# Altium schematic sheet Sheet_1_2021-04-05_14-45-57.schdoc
size 231 x 139 mm
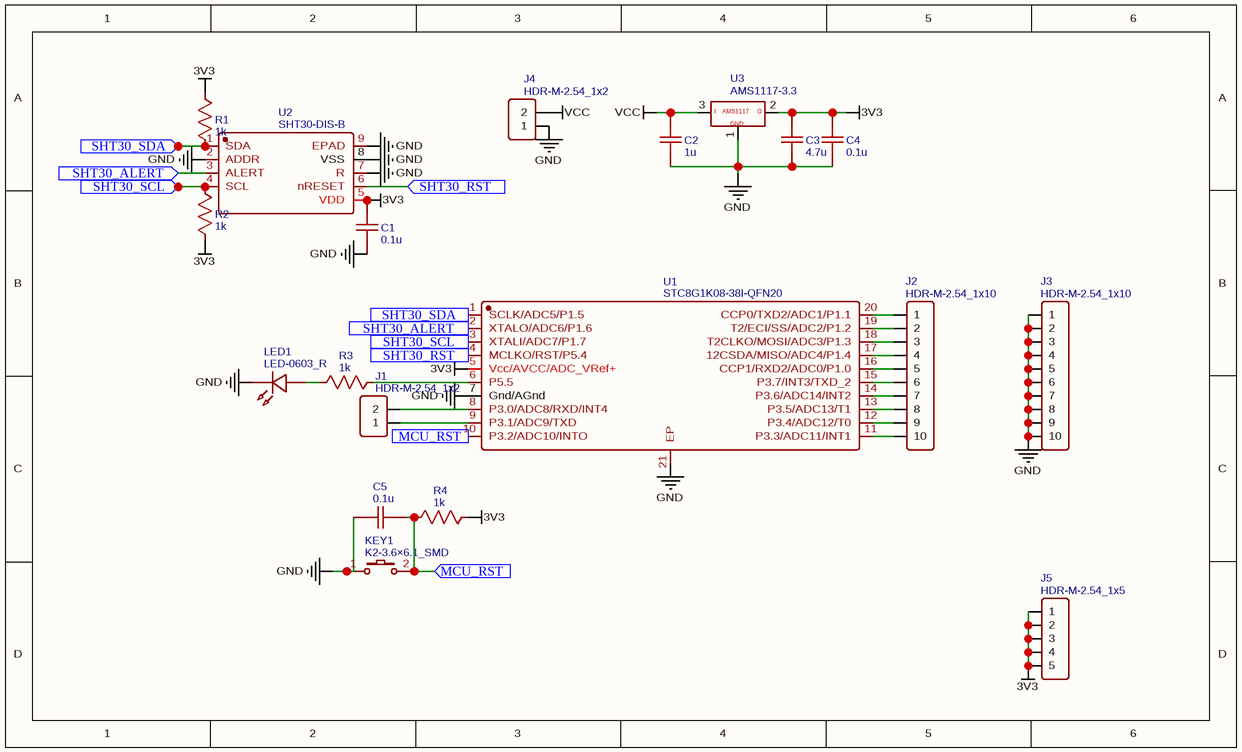
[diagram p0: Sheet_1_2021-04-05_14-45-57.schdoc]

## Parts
C1  0.1u  [C0603]
C2  1u  [C0603]
C3  4.7u  [C0603]
C4  0.1u  [C0603]
C5  0.1u  [C0603]
J1  HDR-M-2.54_1x2  [HDR-M-2.54_1X2]
J2  HDR-M-2.54_1x10  [HDR-M-2.54_1X10]
J3  HDR-M-2.54_1x10  [HDR-M-2.54_1X10]
J4  HDR-M-2.54_1x2  [HDR-M-2.54_1X2]
J5  HDR-M-2.54_1x5  [HDR-M-2.54_1X5]
KEY1  K2-3.6×6.1_SMD  [KEY-SMD_2P-L6.2-W3.6-LS8.0]
LED1  LED-0603_R  [LED0603_RED]
R1  1k  [R0603]
R2  1k  [R0603]
R3  1k  [R0603]
R4  1k  [R0603]
U1  STC8G1K08-38I-QFN20  [TQFN-20L_L3.0-W3.0-P0.40-BL-EP]
U2  SHT30-DIS-B  [DFN-8_L2.5-W2.5-P0.50-BL-EP]
U3  AMS1117-3.3  [SOT-89]

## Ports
MCU_RST (in), SHT30_ALERT (in), SHT30_RST (in), SHT30_SCL (in), SHT30_SDA (in)

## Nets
3V3: C1.2 C3.2 C4.2 J5.1 J5.2 J5.3 J5.4 J5.5 R1.2 R2.1 R4.1 U1.5(Vcc/AVCC/ADC_VRef+) U2.5(VDD) U3.2
GND: C1.1 C2.1 C3.1 C4.1 C5.1 J3.1 J3.2 J3.3 J3.4 J3.5 J3.6 J3.7 J3.8 J3.9 J3.10 J4.1 KEY1.1 LED1.2 U1.7(Gnd/AGnd) U1.21(EP) U2.2(ADDR) U2.7(R) U2.8(VSS) U2.9(EPAD) U3.1
VCC: C2.2 J4.2 U3.3
MCU_RST: C5.2 KEY1.2 R4.2 U1.10(P3.2/ADC10/INTO) ; port MCU_RST
SHT30_ALERT: U1.2(XTALO/ADC6/P1.6) U2.3(ALERT) ; port SHT30_ALERT
SHT30_RST: U1.4(MCLKO/RST/P5.4) U2.6(nRESET) ; port SHT30_RST
SHT30_SCL: R2.2 U1.3(XTALI/ADC7/P1.7) U2.4(SCL) ; port SHT30_SCL
SHT30_SDA: R1.1 U1.1(SCLK/ADC5/P1.5) U2.1(SDA) ; port SHT30_SDA
NetJ1_1: J1.1 U1.9(P3.1/ADC9/TXD)
NetJ1_2: J1.2 U1.8(P3.0/ADC8/RXD/INT4)
NetJ2_1: J2.1 U1.20(CCP0/TXD2/ADC1/P1.1)
NetJ2_2: J2.2 U1.19(T2/ECI/SS/ADC2/P1.2)
NetJ2_3: J2.3 U1.18(T2CLKO/MOSI/ADC3/P1.3)
NetJ2_4: J2.4 U1.17(12CSDA/MISO/ADC4/P1.4)
NetJ2_5: J2.5 U1.16(CCP1/RXD2/ADC0/P1.0)
NetJ2_6: J2.6 U1.15(P3.7/INT3/TXD_2)
NetJ2_7: J2.7 U1.14(P3.6/ADC14/INT2)
NetJ2_8: J2.8 U1.13(P3.5/ADC13/T1)
NetJ2_9: J2.9 U1.12(P3.4/ADC12/T0)
NetJ2_10: J2.10 U1.11(P3.3/ADC11/INT1)
NetLED1_1: LED1.1 R3.1
NetR3_2: R3.2 U1.6(P5.5)

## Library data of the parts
C1 C4 C5 = 0.1u: nameAlias: Value(F); Contributor: LCEDA_Lib
C2 = 1u: nameAlias: Value(F); Contributor: LCEDA_Lib
C3 = 4.7u: nameAlias: Value(F); Contributor: LCEDA_Lib
J1 J4 = HDR-M-2.54_1x2: Contributor: LCEDA_Lib
J2 J3 = HDR-M-2.54_1x10: Contributor: LCEDA_Lib
J5 = HDR-M-2.54_1x5: Contributor: LCEDA_Lib
KEY1 = K2-3.6×6.1_SMD: BOM_Manufacturer Part: K2-1107ST-A4SW-06; Contributor: LCEDA_Lib; 制造商: 韩国韩荣
LED1 = LED-0603_R: BOM_Manufacturer: EVERLIGHT(台湾亿光); BOM_Manufacturer Part: 19-217/R6C-AL1M2VY/3T; Contributor: LCEDA_01
R1-R4 = 1k: nameAlias: Value(Ω); Contributor: LCEDA_Lib
U1 = STC8G1K08-38I-QFN20: BOM_Manufacturer: STC Micro; Contributor: LCSC; BOM_Paste Type: expand
U2 = SHT30-DIS-B: BOM_Manufacturer: Sensirion; BOM_Paste Type: recommend
U3 = AMS1117-3.3: Contributor: hdlazyhy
